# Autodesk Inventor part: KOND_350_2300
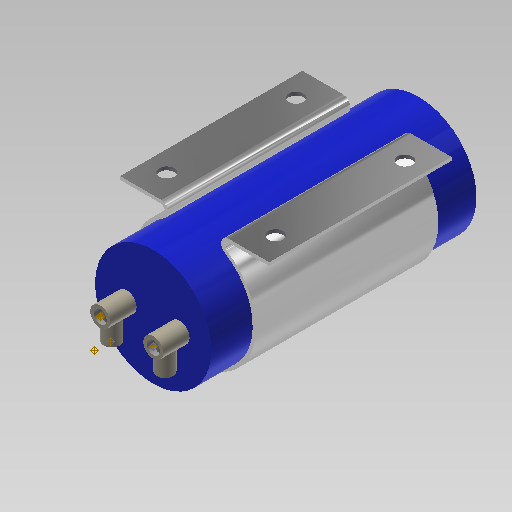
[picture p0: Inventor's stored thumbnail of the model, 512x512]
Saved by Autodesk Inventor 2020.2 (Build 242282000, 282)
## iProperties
GlobalPropertyList: <PropertyList/>
Manager: www.cadconsulting.pl
Company: Fabian Stasiak CAD Consulting
Created: 2014-09
Part Number: KOND_350_2300
Material: Ogólny
Document SubType Name: Modeling
Designer: F.Stasiak
Density: 1 g/cm^3
Appearance: Domyślna
Categories: <MemberInstance><Categories><Category DisplayName="" Mnemonic="CABLEANDHARNESS" InternalName="e4a7e005-5e42-4d16-b293-125e7f0d0512"><Category DisplayName="" Mne
Catalog Web Link: www.expertbooks.pl
Author: F.Stasiak
Subject: Zbiór ćwiczeń. Autodesk Inventor 2020. Kurs Professional
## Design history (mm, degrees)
sketch "Szkic1"
  geometry: C1 r 17.5 at (0, 0); 1 further point
  constraints: 1 centre point, 1 coincident
  dimensions: "d0" = 35 diameter of C1
extrude "Wyciągnięcie proste1" new body sketch "Szkic1" stored distance "d1" = 80; taper "d2" = 0 deg
sketch "Szkic3"
  geometry: L1 (-22.5, 19.248)-(-10.316, 19.248); L2 (-22.5, 19.248)-(-22.5, 18.248); L3 (-22.5, 18.248)-(-10.316, 18.248); L4 (22.5, 19.248)-(10.316, 19.248); L5 (22.5, 19.248)-(22.5, 18.248); L6 (22.5, 18.248)-(10.316, 18.248); C1 r 17.5 at (0, 0) reference; A1 r 18.5 centre (0, 0) between (-9.559, 15.839) and (9.559, 15.839); A2 r 2.324 centre (-10.316, 16.925) between (-9.019, 14.997) and (-10.316, 19.248); A3 r 1.324 centre (-10.316, 16.925) between (-9.698, 15.754) and (-10.316, 18.248); A4 r 2.324 centre (10.316, 16.925) between (10.316, 19.248) and (9.019, 14.997); A5 r 1.324 centre (10.316, 16.925) between (10.316, 18.248) and (9.698, 15.754); A6 r 17.5 centre (0, 0) between (-9.019, 14.997) and (9.019, 14.997); 1 further point
  constraints: 15 point on circle, 12 end point, 6 centre point, 2 concentric, 2 tangent, 1 horizontal, 1 perpendicular, 1 vertical
  dimensions: "d7" = 1 distance of L1.start L2.end; "d8" = 45 distance between parallel lines of L5 L2
extrude "Wyciągnięcie proste2" join sketch "Szkic3" stored distance "d9" = 55; taper "d10" = 0 deg
sketch "Szkic4"
  geometry: L1 (32.816, 55)-(32.816, 0) reference; L2 (45, 0)-(32.816, 0) reference; L3 (45, 55)-(45, 0) reference; L4 (32.816, 55)-(45, 55) reference; L5 (0, 0)-(0, 55) reference; L6 (12.184, 0)-(0, 0) reference; L7 (12.184, 55)-(12.184, 0) reference; L8 (0, 55)-(12.184, 55) reference; L9 (32.816, 55)-(45, 55) reference; L10 (38.908, 55)-(38.908, 0); L11 (5, 0)-(40, 0) reference; L12 (12.184, 55)-(0, 55) reference; L13 (6.092, 55)-(6.092, 0); L14 (38.908, 8)-(6.092, 8); L15 (6.092, 8)-(6.092, 47); L16 (6.092, 47)-(38.908, 47); L17 (38.908, 47)-(38.908, 8); 3 further points
  constraints: 12 end point, 6 point on line, 3 perpendicular, 2 midpoint, 2 parallel, 1 horizontal
  dimensions: "d12" = 8 distance between parallel lines of L11 L14; "d13" = 8 distance between parallel lines of L16 L8 (= d12)
hole "Otwór1" sketch "Szkic4" at (38.908, 8), (6.092, 47), (6.092, 8), (38.908, 47) diameter "d14" = 4.5; stored, may be unused: countersink angle "d18" = 90 deg, drill point angle "d20" = 118 deg; dims "d15" = 6, "d16" = 4, "d17" = 2, "d19" = 2
sketch "Szkic5"
  geometry: L1 (-8, 0)-(8, 0); C1 r 3 at (-8, 0); C2 r 3 at (8, 0); 2 further points
  constraints: 2 centre point, 2 end point, 1 coincident, 1 equal radius, 1 horizontal, 1 midpoint
  dimensions: "d21" = 6 diameter of C1; "d22" = 16 distance of L1.start L1.end
extrude "Wyciągnięcie proste3" join sketch "Szkic5" distance "d23" = 8; taper "d24" = 0 deg
sketch "Szkic6"
  geometry: L1 (11, 48)-(5, 48) reference; L2 (-5, 48)-(-11, 48) reference; C1 r 2.5 at (8, 44.5); C2 r 2.5 at (-8, 44.5); 3 further points
  constraints: 2 centre point, 2 midpoint, 2 vertical alignment, 1 equal radius
  dimensions: "d25" = 5 diameter of C1; "d34" = 3.5 distance from line of L1 C1.centre; "d35" = 3.5 distance from line of L2 C2.centre (= d34)
extrude "Wyciągnięcie proste4" join sketch "Szkic6" distance "d26" = 8; taper "d27" = 0 deg
sketch "Szkic10"
  geometry: C1 r 3 at (0, 0) reference; C2 r 3 at (16, 0) reference; C3 r 2 at (0, 0); C4 r 2 at (16, 0); 1 further point
  constraints: 2 centre point, 2 coincident, 1 equal radius
  dimensions: "d36" = 4 diameter of C3
extrude "Wyciągnięcie proste6" cut sketch "Szkic10" distance "d37" = 10; taper "d38" = 0 deg
sketch "Szkic11"
  geometry: C1 r 2.5 at (0, 0) reference; C2 r 2.5 at (16, 0) reference; C3 r 2 at (0, 0); C4 r 2 at (16, 0); 1 further point
  constraints: 2 centre point, 2 coincident
  dimensions: "d39" = 4 diameter of C3; "d40" = 4 diameter of C4
extrude "Wyciągnięcie proste7" cut sketch "Szkic11" distance "d41" = 8; taper "d42" = 0 deg
node "Płaszczyzna konstrukcyjna4"
node "Płaszczyzna konstrukcyjna5"
node "Punkt konstrukcyjny5"
node "Punkt konstrukcyjny6"
sketch "Szkic12"
  geometry: C1 r 2 at (0, 0) reference
node "C1"
sketch "Szkic13"
  geometry: C1 r 2 at (0, 0) reference
node "C2"
node "Bryła1"
node "Pętla rzutowana1"
node "Pętla rzutowana2"
node "Pętla rzutowana4"
node "Pętla rzutowana5"
node "Pętla rzutowana6"
other parameters: "d43" = 5, "d44" = 5
